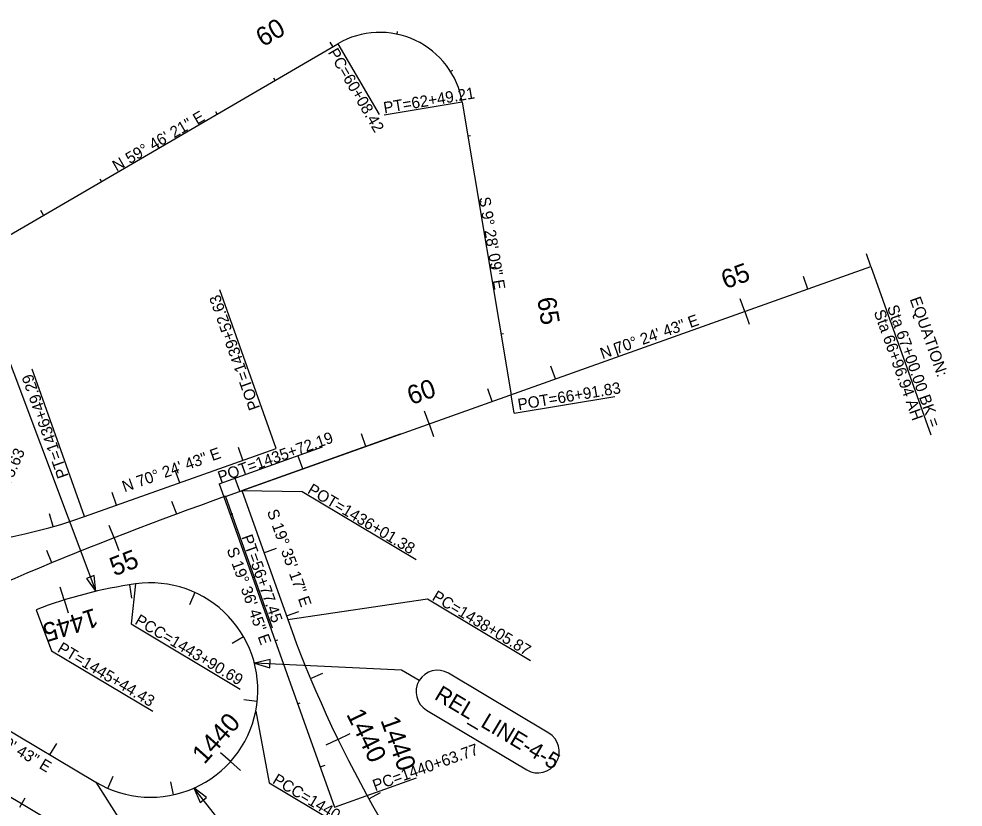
# Model space of a CAD drawing. Extents: x 2339300 to 2355400, y 360879 to 381052.
# Drawn here: x 2349719 to 2351128, y 367862 to 369038 of the extents above; entities that cross this region are included whole.
import ezdxf

# ---------------------------------------------------------------- set-up
doc = ezdxf.new("R2010")
doc.units = 0
for name, color, linetype in [('RD_HC_Cl', 7, 'Continuous'), ('RD_HC_CL_Rel', 7, 'Continuous'), ('RD_HC_Data', 7, 'Continuous'), ('RD_HC_Data_Rel', 7, 'Continuous'), ('RD_HC_Data_Tic', 7, 'Continuous'), ('RD_HC_Data_Tic_Rel', 7, 'Continuous'), ('RD_HC_TX_Rel_Sta50', 7, 'Continuous'), ('RD_HC_TX_Sta50', 7, 'Continuous')]:
    doc.layers.add(name, color=color, linetype=linetype)

msp = doc.modelspace()

# ---------------------------------------------------------------- linework, layer by layer
at = {"layer": 'RD_HC_Cl'}
for p, q in [((2349672.8, 368697), (2350194.7, 369001.1)), ((2350380.3, 368914), (2350453.1, 368477.4)), ((2350027, 368325.7), (2350990.3, 368668.5)), ((2350024.7, 368324.9), (2350189.7, 367861.9))]:
    msp.add_line(p, q, dxfattribs=at)
for centre, radius, start, end in [((2350257.4, 368893.5), 124.6, 9.4691, 120.2274), ((2351947.8, 362927.7), 5729.6, 109.58804, 115.94073)]:
    msp.add_arc(centre, radius, start, end, dxfattribs=at)
at = {"layer": 'RD_HC_CL_Rel'}
for p, q in [((2348614.8, 368528.3), (2351127.8, 367029)), ((2349328.8, 368200.1), (2349833.3, 367899.1))]:
    msp.add_line(p, q, dxfattribs=at)
for centre, radius, start, end in [((2349988.4, 367521.7), 680, 98.078, 111.0317), ((2349915.3, 368036.5), 160, 348.6282, 98.078), ((2349915.3, 368036.5), 160, 239.1785, 348.6282)]:
    msp.add_arc(centre, radius, start, end, dxfattribs=at)
at = {"layer": 'RD_HC_Data'}
for p, q in [((2350194.7, 369001.1), (2350256.3, 368895.4)), ((2350380.3, 368914), (2350264, 368894.6)), ((2350990.3, 368668.5), (2351079.7, 368417.4)), ((2350457.7, 368449.7), (2350453.1, 368477.4)), ((2350457.7, 368449.7), (2350607.8, 368474.8)), ((2350017.7, 368344.6), (2350171.8, 368399.5)), ((2350017.7, 368344.6), (2350024.7, 368324.9)), ((2350027, 368325.7), (2350096.9, 368129.3)), ((2350509.5, 367972.4), (2350359.9, 368061.7)), ((2350327.1, 368006.7), (2350476.7, 367917.4)), ((2350189.7, 367861.9), (2350312.2, 367905.5))]:
    msp.add_line(p, q, dxfattribs=at)
for points in [[(2349625.3, 368645.6), (2349669.2, 368619.5), (2349833.4, 368183.8)], [(2350316, 368050.6), (2350289.5, 368066.4), (2350070.1, 368076.9)], [(2350097.8, 367757.7), (2350071.6, 367773.3), (2349979.6, 367890.6)]]:
    msp.add_lwpolyline(points, dxfattribs=at)
for points in [[(2349819.4, 368203.3), (2349833.4, 368183.8), (2349831, 368207.7)], [(2350093.5, 368082), (2350070.1, 368076.9), (2350093, 368069.6)], [(2349998.8, 367876.2), (2349979.6, 367890.6), (2349989, 367868.5)]]:
    msp.add_lwpolyline(points, close=True, dxfattribs=at)
for centre, start, end in [((2350343.5, 368034.2), 59.1784, 239.1784), ((2350493.1, 367944.9), 239.1784, 59.1784)]:
    msp.add_arc(centre, 32, start, end, dxfattribs=at)
at = {"layer": 'RD_HC_Data_Rel'}
for p, q in [((2350102.5, 368397.2), (2350018.4, 368633.7)), ((2349816.7, 368295.5), (2349738.4, 368515.6)), ((2350051.3, 368334.4), (2350288.4, 368418.8)), ((2349816.7, 368295.5), (2350102.5, 368397.2)), ((2350051.3, 368334.4), (2350119.9, 368141.7))]:
    msp.add_line(p, q, dxfattribs=at)
for points in [[(2350051.3, 368334.4), (2350141.4, 368332.8), (2350311.4, 368231.3)], [(2349892.8, 368194.9), (2349886.5, 368135.2), (2350049.1, 368038.1)], [(2350119.9, 368141.7), (2350328.4, 368172.7), (2350482.2, 368080.9)], [(2349744.3, 368156.4), (2349767.5, 368095.3), (2349918.4, 368005.3)], [(2350072.1, 368005), (2350092.2, 367898.3), (2350256.6, 367800.3)], [(2349833.3, 367899.1), (2349867.6, 367845.8), (2350027.4, 367750.5)]]:
    msp.add_lwpolyline(points, dxfattribs=at)
for centre, radius, start, end in [((2349557.9, 369022.8), 772, 245.8825, 289.588), ((2351779.9, 368732.5), 1762, 199.588, 239.1733)]:
    msp.add_arc(centre, radius, start, end, dxfattribs=at)
at = {"layer": 'RD_HC_Data_Tic'}
for p, q in [((2350283.1, 369015.4), (2350283.9, 369019.3)), ((2350187.4, 368996.9), (2350183.4, 369003.8)), ((2350101, 368946.5), (2350099, 368950)), ((2350362.9, 368959.7), (2350366.3, 368961.8)), ((2350014.6, 368896.2), (2350012.6, 368899.6)), ((2350388.7, 368863.9), (2350392.6, 368864.5)), ((2349928.2, 368845.8), (2349926.2, 368849.3)), ((2349841.8, 368795.5), (2349839.8, 368799)), ((2350405.1, 368765.2), (2350409, 368765.9)), ((2349755.4, 368745.2), (2349751.4, 368752.1)), ((2350990.3, 368668.5), (2350983.6, 368687.4)), ((2350421.6, 368666.6), (2350429.4, 368667.9)), ((2350896.1, 368635), (2350889.4, 368653.9)), ((2350801.9, 368601.5), (2350795.2, 368620.3)), ((2350801.9, 368601.5), (2350808.6, 368582.7)), ((2350438, 368568), (2350442, 368568.6)), ((2350613.5, 368534.4), (2350606.8, 368553.3)), ((2350519.3, 368500.9), (2350512.6, 368519.8)), ((2350425.1, 368467.4), (2350418.3, 368486.2)), ((2350330.8, 368433.9), (2350324.1, 368452.7)), ((2350330.8, 368433.9), (2350337.5, 368415)), ((2350236.6, 368400.3), (2350229.9, 368419.2)), ((2350142.4, 368366.8), (2350135.7, 368385.7)), ((2350048.2, 368333.3), (2350041.5, 368352.1)), ((2349954.2, 368299.3), (2349947.2, 368318)), ((2350034, 368298.7), (2350037.8, 368300.1)), ((2349860.7, 368263.7), (2349853.4, 368282.3)), ((2349860.7, 368263.7), (2349868, 368245)), ((2349767.9, 368226.4), (2349760.3, 368244.9)), ((2350067.6, 368204.5), (2350071.3, 368205.9)), ((2350101.1, 368110.3), (2350104.9, 368111.7)), ((2350134.7, 368016.1), (2350138.5, 368017.5)), ((2350168.3, 367921.9), (2350175.8, 367924.6))]:
    msp.add_line(p, q, dxfattribs=at)
at = {"layer": 'RD_HC_Data_Tic_Rel'}
for p, q in [((2350052.9, 368379.6), (2350046.2, 368398.4)), ((2349958.7, 368346), (2349952, 368364.9)), ((2349864.5, 368312.5), (2349857.8, 368331.4)), ((2349769.8, 368280.5), (2349764.3, 368299.7)), ((2350084.4, 368241.5), (2350103.2, 368248.2)), ((2350084.4, 368241.5), (2350103.2, 368248.2)), ((2349786.3, 368171), (2349780.3, 368190.1)), ((2349883.6, 368193.6), (2349886.7, 368173.8)), ((2349981.4, 368182.2), (2349973.1, 368164)), ((2349786.3, 368171), (2349792.2, 368151.9)), ((2350117.9, 368147.3), (2350136.7, 368154)), ((2350117.9, 368147.3), (2350136.7, 368154)), ((2350054.1, 368116), (2350036.8, 368106.1)), ((2350153.8, 368053.9), (2350172.2, 368061.6)), ((2350153.8, 368053.9), (2350172.2, 368061.6)), ((2350074.4, 368019.7), (2350054.5, 368021.8)), ((2350194.9, 367962.8), (2350176.9, 367954.1)), ((2350194.9, 367962.8), (2350176.9, 367954.1)), ((2350194.9, 367962.8), (2350212.9, 367971.5)), ((2350194.9, 367962.8), (2350212.9, 367971.5)), ((2349765.1, 367939.8), (2349775.4, 367957)), ((2350034.5, 367929.8), (2350019.6, 367943.1)), ((2350034.5, 367929.8), (2350049.4, 367916.5)), ((2349851.6, 367889.7), (2349859.6, 367908.1)), ((2349949.5, 367880.2), (2349945.3, 367899.8)), ((2350241.1, 367874.1), (2350258.5, 367883.9)), ((2350241.1, 367874.1), (2350258.5, 367883.9)), ((2349719.9, 367862), (2349728.1, 367875.7))]:
    msp.add_line(p, q, dxfattribs=at)

# ---------------------------------------------------------------- texts
at = {"layer": 'RD_HC_Data'}
for s, height, rotation, p in [('PC=60+08.42', 17, 300.2274, (2350179.4, 368988.4)), ('PT=62+49.21', 17, 9.4691, (2350264.2, 368897.1)), ('N 59%%d 46\' 21" E', 17, 30.2274, (2349864.5, 368809.9)), ('S 9%%d 28\' 09" E', 17, 279.4691, (2350405.1, 368771.3)), ('Sta 67+00.00 BK = ', 17, 289.588, (2351014, 368608)), ('EQUATION:', 17, 289.588, (2351047.9, 368620.1)), ('N 70%%d 24\' 43" E', 17, 19.588, (2350589.7, 368530.2)), ('Sta 66+96.94 AH', 17, 289.588, (2350994.2, 368600.9)), ('POT=66+91.83', 17, 9.4691, (2350464.6, 368454.2)), ('POT=1435+72.19', 17, 19.6124, (2350019.1, 368345.9)), ('POT=1434+75.63', 17, 65.9774, (2349654.6, 368227.7)), ('PT=56+77.45', 17, 289.588, (2350050.6, 368265.2)), ('S 19%%d 36\' 45" E', 17, 289.6124, (2350028.6, 368246.4)), ('REL_LINE-4-5', 24, 329.1784, (2350337.4, 368023.9)), ('PC=1440+63.77', 17, 19.6124, (2350250.2, 367885.6))]:
    msp.add_text(s, height=height, rotation=rotation, dxfattribs=at).set_placement(p)
at = {"layer": 'RD_HC_Data_Rel'}
for s, rotation, p in [('POT=1439+52.63', 109.588, (2350078.8, 368457.8)), ('PT=1436+49.29', 109.588, (2349793.1, 368356.1)), ('N 70%%d 24\' 43" E', 19.588, (2349876.4, 368331.6)), ('POT=1436+01.38', 329.1784, (2350148, 368331.2)), ('S 19%%d 35\' 17" E', 289.588, (2350088.7, 368303)), ('PC=1438+05.87', 329.1784, (2350334, 368171.7)), ('PCC=1443+90.69', 329.1784, (2349890.4, 368136.1)), ('PT=1445+44.43', 329.1784, (2349774.8, 368094.5)), ('S 59%%d 10\' 43" E', 329.1785, (2349629.3, 367991.2)), ('PCC=1440+85.05', 329.1784, (2350095.9, 367898.3))]:
    msp.add_text(s, height=17, rotation=rotation, dxfattribs=at).set_placement(p)
at = {"layer": 'RD_HC_TX_Rel_Sta50'}
for s, rotation, p in [('1445', 197.2879, (2349831.4, 368159.2)), ('1440', 295.9006, (2350206.9, 368000.5)), ('1440', 48.171, (2349995.4, 367924.6))]:
    msp.add_text(s, height=28, rotation=rotation, dxfattribs=at).set_placement(p)
at = {"layer": 'RD_HC_TX_Sta50'}
for s, rotation, p in [('60', 30.2274, (2350082.8, 368995.7)), ('65', 19.588, (2350772.9, 368634.7)), ('65', 279.4691, (2350492, 368621)), ('60', 19.588, (2350304.2, 368461.7)), ('55', 21.3625, (2349861.1, 368206.1)), ('1440', 289.6124, (2350258, 367991.7))]:
    msp.add_text(s, height=28, rotation=rotation, dxfattribs=at).set_placement(p)

doc.saveas('drawing.dxf')
